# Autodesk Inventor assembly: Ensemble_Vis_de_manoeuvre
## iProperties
Shininess: 64.0
Length Units: 11269
Angle Units: 11279
Time Units: 11290
Mass Units: 11283
Length Display Precision: 3
Angle Display Precision: 2
Compacted: True
Created: 2004-05
Part Number: Ensemble_Vis_de_manoeuvre
Document SubType Name: Assembly
Designer: David
Density: 0.0
Volumn: 0.0
Area: 0.0
PropertySet Name: Model Information
Control State: 0
Master: False
Checked Out: False
Author: David
